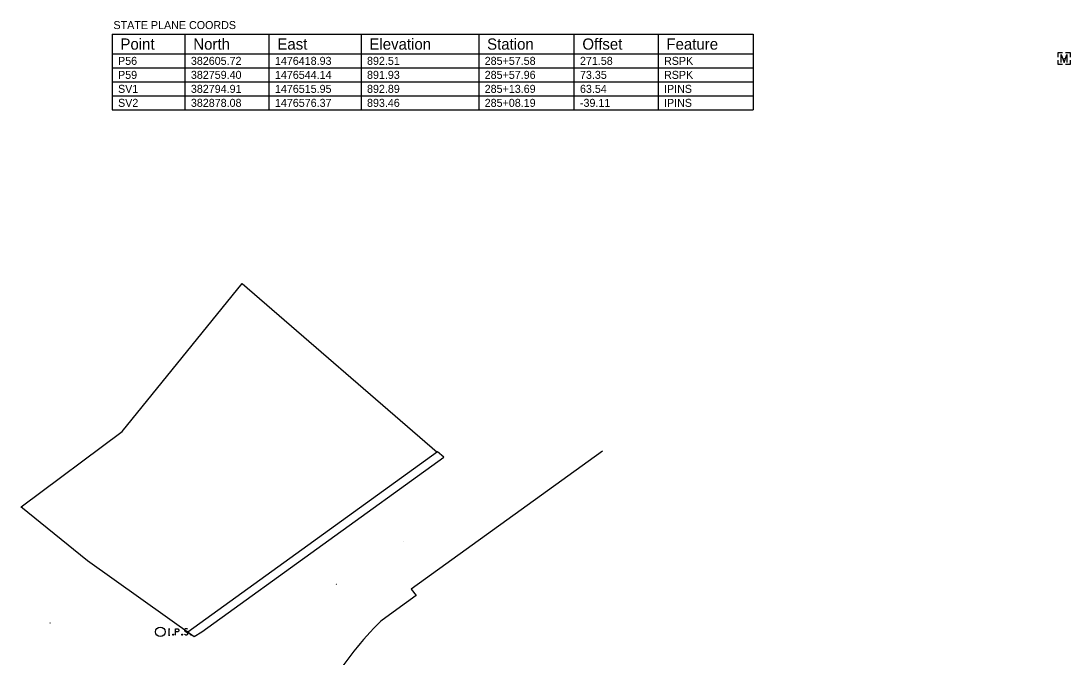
# Model space of a CAD drawing. Extents: x 1474121 to 1496246, y 375240 to 390007.
# Drawn here: x 1476489 to 1477145, y 382862 to 383260 of the extents above; entities that cross this region are included whole.
import ezdxf

# ---------------------------------------------------------------- set-up
doc = ezdxf.new("R2010")
doc.units = 0
for name, color, linetype in [('DV_X_Property_Line', 7, 'Continuous'), ('RW_X_CL_20', 7, 'Continuous'), ('RW_X_Fee_RW', 7, 'Continuous'), ('SV_P_Mon_Cells_Set', 7, 'Continuous'), ('SV_X_Random_Point', 7, 'Continuous'), ('SV_X_Shot_Marker', 7, 'Continuous'), ('SV_X_Text', 7, 'Continuous'), ('SV_X_Text_Elevation', 7, 'Continuous'), ('SV_X_Text_Name', 7, 'Continuous'), ('VG_X_Cells', 7, 'Continuous')]:
    doc.layers.add(name, color=color, linetype=linetype)

msp = doc.modelspace()

# ---------------------------------------------------------------- linework, layer by layer
at = {"layer": 'DV_X_Property_Line'}
msp.add_lwpolyline([(1476489.36, 382956.28), (1476552.48, 383003.4), (1476627.56, 383095.93), (1476749.26, 382990.49)], dxfattribs=at)
at = {"layer": 'RW_X_CL_20'}
msp.add_line((1477140.75, 383236.47), (1477140.75, 383236.47), dxfattribs=at)
msp.add_line((1477140.75, 383236.47), (1477140.75, 383236.47), dxfattribs=at)
for points in [[(1477137, 383237.42), (1477137, 383240.22), (1477139.81, 383240.22)], [(1477139.81, 383232.72), (1477137, 383232.72), (1477137, 383235.52)], [(1477138.9, 383233.97), (1477138.9, 383238.97), (1477140.75, 383233.97), (1477142.6, 383238.97), (1477142.6, 383233.97)], [(1477140.68, 383236.49), (1477140.68, 383236.55), (1477140.73, 383236.55)], [(1477140.73, 383236.39), (1477140.68, 383236.39), (1477140.68, 383236.45)], [(1477140.71, 383236.42), (1477140.71, 383236.52), (1477140.75, 383236.42), (1477140.79, 383236.52), (1477140.79, 383236.42)], [(1477140.77, 383236.55), (1477140.83, 383236.55), (1477140.83, 383236.49)], [(1477140.83, 383236.45), (1477140.83, 383236.39), (1477140.77, 383236.39)], [(1477141.64, 383240.22), (1477144.51, 383240.22), (1477144.51, 383237.42)], [(1477144.51, 383235.52), (1477144.51, 383232.72), (1477141.64, 383232.72)]]:
    msp.add_lwpolyline(points, dxfattribs=at)
at = {"layer": 'RW_X_Fee_RW'}
for p, q in [((1476749.44, 382990.62), (1476593.51, 382877.9)), ((1476602.18, 382878.08), (1476753.33, 382987.24)), ((1476602.18, 382878.08), (1476753.33, 382987.24)), ((1476852.58, 382991.14), (1476733.09, 382904.76)), ((1476753.33, 382987.24), (1476749.44, 382990.62)), ((1476489.27, 382956.35), (1476530.81, 382922.63)), ((1476530.81, 382922.63), (1476597.4, 382875.13)), ((1476736.05, 382900.73), (1476724.01, 382892.03)), ((1476733.09, 382904.76), (1476736.05, 382900.73)), ((1476724.01, 382892.03), (1476713.99, 382884.8)), ((1476593.51, 382877.9), (1476597.4, 382875.13)), ((1476597.4, 382875.13), (1476602.18, 382878.08)), ((1476597.4, 382875.13), (1476602.18, 382878.08))]:
    msp.add_line(p, q, dxfattribs=at)
msp.add_arc((1476865.27, 382733.44), 214, 134.98461, 148.44264, dxfattribs=at)
at = {"layer": 'SV_P_Mon_Cells_Set'}
for points in [[(1476581.42, 382880.08), (1476582.3, 382880.08)], [(1476581.42, 382876.08), (1476582.3, 382876.08)], [(1476581.86, 382876.08), (1476581.86, 382880.08)], [(1476584.25, 382876.62), (1476584.39, 382876.62), (1476584.47, 382876.55), (1476584.56, 382876.43), (1476584.56, 382876.27), (1476584.47, 382876.15), (1476584.39, 382876.08), (1476584.25, 382876.08), (1476584.17, 382876.15), (1476584.09, 382876.27), (1476584.09, 382876.43), (1476584.17, 382876.55), (1476584.25, 382876.62)], [(1476585.77, 382876.08), (1476585.77, 382880.08), (1476587.09, 382880.08), (1476587.23, 382880.05), (1476587.42, 382879.99), (1476587.51, 382879.92), (1476587.59, 382879.86), (1476587.7, 382879.7), (1476587.78, 382879.55), (1476587.84, 382879.29), (1476587.84, 382878.92), (1476587.81, 382878.79), (1476587.75, 382878.6), (1476587.64, 382878.38), (1476587.53, 382878.29), (1476587.45, 382878.22), (1476587.31, 382878.16), (1476587.09, 382878.13), (1476585.77, 382878.13)], [(1476589.88, 382876.62), (1476590.01, 382876.62), (1476590.1, 382876.55), (1476590.18, 382876.43), (1476590.18, 382876.27), (1476590.1, 382876.15), (1476590.01, 382876.08), (1476589.88, 382876.08), (1476589.79, 382876.15), (1476589.71, 382876.27), (1476589.71, 382876.43), (1476589.79, 382876.55), (1476589.88, 382876.62)], [(1476593.29, 382879.8), (1476593.24, 382879.86), (1476593.15, 382879.92), (1476592.91, 382880.02), (1476592.6, 382880.08), (1476592.38, 382880.08), (1476592.3, 382880.08), (1476591.94, 382879.99), (1476591.64, 382879.8), (1476591.45, 382879.55), (1476591.39, 382879.29), (1476591.39, 382879.11), (1476591.45, 382878.85), (1476591.67, 382878.63), (1476593.18, 382877.69), (1476593.32, 382877.56), (1476593.38, 382877.44), (1476593.43, 382877.25), (1476593.43, 382877.06), (1476593.4, 382876.87), (1476593.38, 382876.74), (1476593.32, 382876.59), (1476593.27, 382876.46), (1476593.21, 382876.37), (1476593.13, 382876.27), (1476593.04, 382876.21), (1476592.93, 382876.15), (1476592.85, 382876.11), (1476592.6, 382876.08), (1476592.22, 382876.08), (1476591.97, 382876.15), (1476591.61, 382876.37), (1476591.39, 382876.55)], [(1476595.33, 382876.62), (1476595.47, 382876.62), (1476595.55, 382876.55), (1476595.64, 382876.43), (1476595.64, 382876.27), (1476595.55, 382876.15), (1476595.47, 382876.08), (1476595.33, 382876.08), (1476595.25, 382876.15), (1476595.17, 382876.27), (1476595.17, 382876.43), (1476595.25, 382876.55), (1476595.33, 382876.62)]]:
    msp.add_lwpolyline(points, dxfattribs=at)
msp.add_circle((1476576.37, 382878.08), 3, dxfattribs=at)
at = {"layer": 'SV_X_Random_Point'}
for p, q in [((1476686.22, 382907.89), (1476686.28, 382907.95)), ((1476686.22, 382907.95), (1476686.28, 382907.89)), ((1476507.47, 382883.57), (1476507.53, 382883.63)), ((1476507.47, 382883.63), (1476507.53, 382883.57))]:
    msp.add_line(p, q, dxfattribs=at)
at = {"layer": 'SV_X_Shot_Marker'}
for p, q in [((1476728.48, 382934.52), (1476728.53, 382934.52)), ((1476728.51, 382934.54), (1476728.51, 382934.49)), ((1476728.51, 382934.52), (1476728.51, 382934.52))]:
    msp.add_line(p, q, dxfattribs=at)
at = {"layer": 'VG_X_Cells'}
for p, q in [((1476546.19, 383251.67), (1476946.69, 383251.67)), ((1476546.19, 383251.67), (1476546.19, 383204.42)), ((1476591.69, 383251.67), (1476591.69, 383204.42)), ((1476644.19, 383251.67), (1476644.19, 383204.42)), ((1476701.69, 383251.67), (1476701.69, 383204.42)), ((1476775.19, 383251.67), (1476775.19, 383204.42)), ((1476834.69, 383251.67), (1476834.69, 383204.42)), ((1476887.19, 383251.67), (1476887.19, 383204.42)), ((1476946.69, 383251.67), (1476946.69, 383204.42)), ((1476946.69, 383251.67), (1476946.69, 383204.42)), ((1476546.19, 383239.42), (1476946.69, 383239.42)), ((1476546.19, 383230.67), (1476946.69, 383230.67)), ((1476546.19, 383230.67), (1476946.69, 383230.67)), ((1476546.19, 383230.67), (1476946.69, 383230.67)), ((1476546.19, 383230.67), (1476946.69, 383230.67)), ((1476546.19, 383230.67), (1476946.69, 383230.67)), ((1476546.19, 383230.67), (1476946.69, 383230.67)), ((1476546.19, 383230.67), (1476946.69, 383230.67)), ((1476546.19, 383221.92), (1476946.69, 383221.92)), ((1476546.19, 383221.92), (1476946.69, 383221.92)), ((1476546.19, 383221.92), (1476946.69, 383221.92)), ((1476546.19, 383221.92), (1476946.69, 383221.92)), ((1476546.19, 383221.92), (1476946.69, 383221.92)), ((1476546.19, 383221.92), (1476946.69, 383221.92)), ((1476546.19, 383221.92), (1476946.69, 383221.92)), ((1476546.19, 383213.17), (1476946.69, 383213.17)), ((1476546.19, 383213.17), (1476946.69, 383213.17)), ((1476546.19, 383213.17), (1476946.69, 383213.17)), ((1476546.19, 383213.17), (1476946.69, 383213.17)), ((1476546.19, 383213.17), (1476946.69, 383213.17)), ((1476546.19, 383213.17), (1476946.69, 383213.17)), ((1476546.19, 383213.17), (1476946.69, 383213.17)), ((1476546.19, 383204.42), (1476946.69, 383204.42)), ((1476546.19, 383204.42), (1476946.69, 383204.42)), ((1476546.19, 383204.42), (1476946.69, 383204.42)), ((1476546.19, 383204.42), (1476946.69, 383204.42)), ((1476546.19, 383204.42), (1476946.69, 383204.42)), ((1476546.19, 383204.42), (1476946.69, 383204.42)), ((1476546.19, 383204.42), (1476946.69, 383204.42))]:
    msp.add_line(p, q, dxfattribs=at)

# ---------------------------------------------------------------- texts
at = {"layer": 'SV_X_Text'}
msp.add_text('STATE PLANE COORDS', height=5, dxfattribs=at).set_placement((1476547.08, 383254.92))
at = {"layer": 'SV_X_Text_Elevation'}
for p in [(1477140.45, 383236.41), (1476728.21, 382934.46), (1476685.95, 382907.86), (1476507.2, 382883.54)]:
    msp.add_text('840.00', height=0.06, dxfattribs=at).set_placement(p)
at = {"layer": 'SV_X_Text_Name'}
for s, p in [('55', (1477140.67, 383236.47)), ('47', (1476728.42, 382934.52)), ('CLRWA1', (1476685.96, 382907.92)), ('BA11', (1476507.35, 382883.6))]:
    msp.add_text(s, height=0.06, dxfattribs=at).set_placement(p)
at = {"layer": 'VG_X_Cells'}
for s, height, p in [('Point', 7, (1476551.44, 383242.05)), ('North', 7, (1476596.94, 383242.05)), ('East', 7, (1476649.44, 383242.05)), ('Elevation', 7, (1476706.94, 383242.05)), ('Station', 7, (1476780.44, 383242.05)), ('Offset', 7, (1476839.94, 383242.05)), ('Feature', 7, (1476892.44, 383242.05)), ('P56', 5, (1476549.94, 383232.55)), ('382605.72', 5, (1476595.44, 383232.55)), ('1476418.93', 5, (1476647.94, 383232.55)), ('892.51', 5, (1476705.44, 383232.55)), ('285+57.58', 5, (1476778.94, 383232.55)), ('271.58', 5, (1476838.44, 383232.55)), ('RSPK', 5, (1476890.94, 383232.55)), ('P59', 5, (1476549.94, 383223.8)), ('382759.40', 5, (1476595.44, 383223.8)), ('1476544.14', 5, (1476647.94, 383223.8)), ('891.93', 5, (1476705.44, 383223.8)), ('285+57.96', 5, (1476778.94, 383223.8)), ('73.35', 5, (1476838.44, 383223.8)), ('RSPK', 5, (1476890.94, 383223.8)), ('SV1', 5, (1476549.94, 383215.05)), ('382794.91', 5, (1476595.44, 383215.05)), ('1476515.95', 5, (1476647.94, 383215.05)), ('892.89', 5, (1476705.44, 383215.05)), ('285+13.69', 5, (1476778.94, 383215.05)), ('63.54', 5, (1476838.44, 383215.05)), ('IPINS', 5, (1476890.94, 383215.05)), ('SV2', 5, (1476549.94, 383206.3)), ('382878.08', 5, (1476595.44, 383206.3)), ('1476576.37', 5, (1476647.94, 383206.3)), ('893.46', 5, (1476705.44, 383206.3)), ('285+08.19', 5, (1476778.94, 383206.3)), ('-39.11', 5, (1476838.44, 383206.3)), ('IPINS', 5, (1476890.94, 383206.3))]:
    msp.add_text(s, height=height, dxfattribs=at).set_placement(p)

doc.saveas('drawing.dxf')
